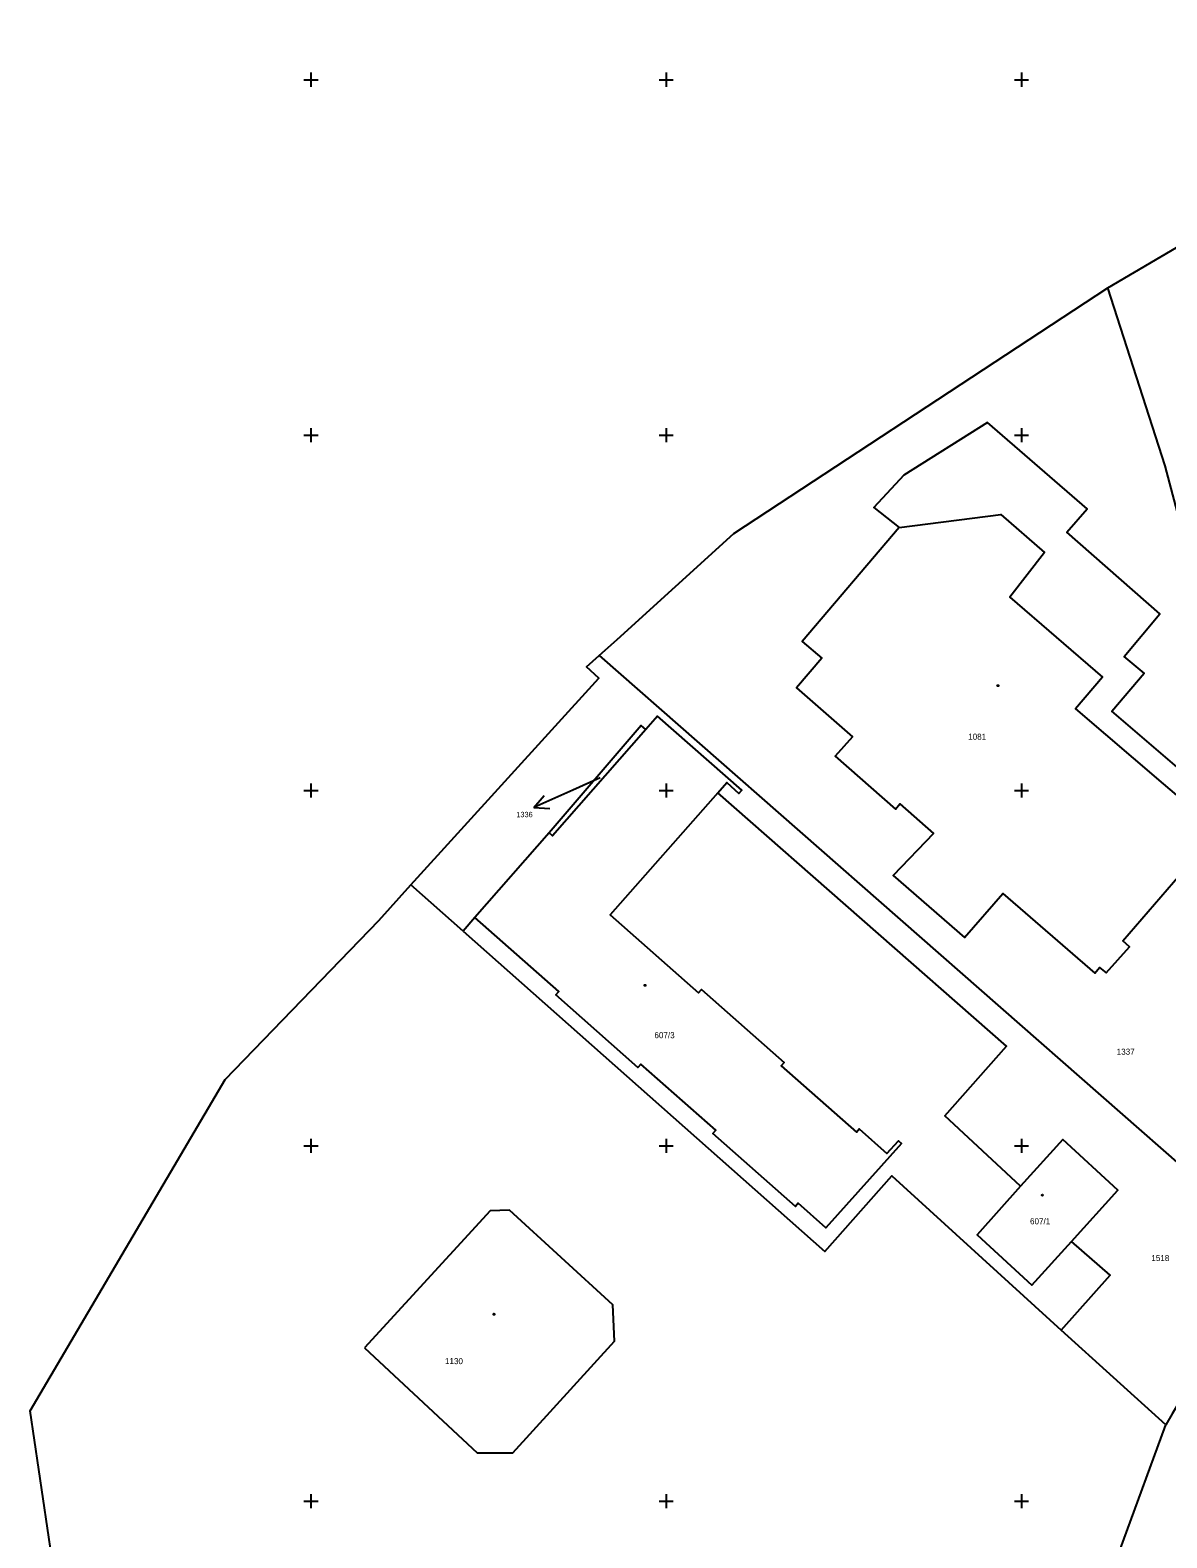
# Model space of a CAD drawing. Extents: x -711234 to -710007, y -1026313 to -1025448.
# Drawn here: x -711044.8 to -710964.8, y -1025852.6 to -1025746.5 of the extents above; entities that cross this region are included whole.
import ezdxf

# ---------------------------------------------------------------- set-up
doc = ezdxf.new("R2010")
doc.units = 0
for name, color, linetype in [('Z_hektometricka_sit', 7, 'Continuous'), ('Z_katastr_cisla_pozemkova', 7, 'Continuous'), ('Z_katastr_cisla_stavebni', 7, 'Continuous'), ('Z_katastr_hranice', 7, 'Continuous'), ('Z_katastr_parcelni_cislo_odkaz', 7, 'Continuous'), ('Z_katastr_vnitrni_kresba', 7, 'Continuous'), ('Z_katastr_znacky_budov', 7, 'Continuous')]:
    doc.layers.add(name, color=color, linetype=linetype)

msp = doc.modelspace()

# ---------------------------------------------------------------- linework, layer by layer
at = {"layer": 'Z_hektometricka_sit'}
for p, q in [((-711025.5, -1025750), (-711024.5, -1025750)), ((-711025, -1025749.5), (-711025, -1025750.5)), ((-711000.5, -1025750), (-710999.5, -1025750)), ((-711000, -1025749.5), (-711000, -1025750.5)), ((-710975.5, -1025750), (-710974.5, -1025750)), ((-710975, -1025749.5), (-710975, -1025750.5)), ((-711025.5, -1025775), (-711024.5, -1025775)), ((-711025, -1025774.5), (-711025, -1025775.5)), ((-711000.5, -1025775), (-710999.5, -1025775)), ((-711000, -1025774.5), (-711000, -1025775.5)), ((-710975.5, -1025775), (-710974.5, -1025775)), ((-710975, -1025774.5), (-710975, -1025775.5)), ((-711025, -1025799.5), (-711025, -1025800.5)), ((-711000, -1025799.5), (-711000, -1025800.5)), ((-710975, -1025799.5), (-710975, -1025800.5)), ((-711025.5, -1025800), (-711024.5, -1025800)), ((-711000.5, -1025800), (-710999.5, -1025800)), ((-710975.5, -1025800), (-710974.5, -1025800)), ((-711025.5, -1025825), (-711024.5, -1025825)), ((-711025, -1025824.5), (-711025, -1025825.5)), ((-711000.5, -1025825), (-710999.5, -1025825)), ((-711000, -1025824.5), (-711000, -1025825.5)), ((-710975.5, -1025825), (-710974.5, -1025825)), ((-710975, -1025824.5), (-710975, -1025825.5)), ((-711025, -1025849.5), (-711025, -1025850.5)), ((-711000, -1025849.5), (-711000, -1025850.5)), ((-710975, -1025849.5), (-710975, -1025850.5)), ((-711025.5, -1025850), (-711024.5, -1025850)), ((-711000.5, -1025850), (-710999.5, -1025850)), ((-710975.5, -1025850), (-710974.5, -1025850))]:
    msp.add_line(p, q, dxfattribs=at)
at = {"layer": 'Z_katastr_hranice'}
for p, q in [((-711004.72, -1025790.51), (-710958.45, -1025831.09)), ((-711008.23, -1025802.99), (-711013.46, -1025808.94)), ((-711014.28, -1025809.91), (-711017.96, -1025806.65)), ((-711013.46, -1025808.94), (-711014.28, -1025809.91)), ((-710964.85, -1025844.62), (-710972.21, -1025837.97))]:
    msp.add_line(p, q, dxfattribs=at)
for points in [[(-710968.93, -1025764.64), (-710955.38, -1025756.68), (-710946.98, -1025752.23), (-710932.82, -1025746.51)], [(-711004.72, -1025790.51), (-711003.46, -1025789.37), (-710995.25, -1025781.93), (-710972.89, -1025767.24), (-710968.93, -1025764.64)], [(-710958.45, -1025831.09), (-710956.97, -1025823.37), (-710960.68, -1025811.62), (-710961.28, -1025808.78), (-710956.91, -1025805.08), (-710961.58, -1025789.66), (-710964.9, -1025777.15), (-710968.93, -1025764.64)], [(-710964.04, -1025798.37), (-710968.65, -1025794.42), (-710966.36, -1025791.75), (-710967.77, -1025790.57), (-710965.26, -1025787.57), (-710971.82, -1025781.82), (-710970.38, -1025780.18), (-710977.39, -1025774.11), (-710983.28, -1025777.81), (-710985.39, -1025780.09), (-710983.6, -1025781.5), (-710990.44, -1025789.51), (-710989.06, -1025790.69), (-710990.83, -1025792.77), (-710986.9, -1025796.22), (-710988.1, -1025797.59), (-710983.87, -1025801.31), (-710983.55, -1025800.95), (-710981.19, -1025803.03), (-710984.03, -1025805.99), (-710979, -1025810.34), (-710976.32, -1025807.24), (-710969.84, -1025812.85), (-710969.5, -1025812.45), (-710969.04, -1025812.84), (-710967.39, -1025811), (-710967.88, -1025810.58), (-710961.19, -1025802.83)], [(-711017.96, -1025806.65), (-711004.74, -1025792.09), (-711005.61, -1025791.31), (-711004.72, -1025790.51)], [(-711001.44, -1025795.71), (-711001.77, -1025795.42), (-711008.23, -1025802.99)], [(-711001.44, -1025795.71), (-711008.01, -1025803.19), (-711008.23, -1025802.99)], [(-710996.37, -1025800.16), (-710995.74, -1025799.44), (-710994.88, -1025800.21), (-710994.68, -1025799.98), (-711000.62, -1025794.77), (-711001.44, -1025795.71)], [(-710996.37, -1025800.16), (-711003.95, -1025808.75), (-710997.72, -1025814.24), (-710997.52, -1025814.01), (-710991.71, -1025819.14), (-710991.91, -1025819.37), (-710986.62, -1025824.03), (-710986.42, -1025823.81), (-710984.47, -1025825.53), (-710983.66, -1025824.64), (-710983.44, -1025824.84), (-710988.77, -1025830.76), (-710990.72, -1025829.04), (-710990.91, -1025829.27), (-710996.72, -1025824.13), (-710996.52, -1025823.91), (-711001.79, -1025819.25), (-711001.99, -1025819.48), (-711007.76, -1025814.37), (-711007.56, -1025814.15), (-711013.46, -1025808.94)], [(-710972.21, -1025837.97), (-710968.75, -1025834.11), (-710971.49, -1025831.73), (-710968.22, -1025828.12), (-710972.1, -1025824.55), (-710975.06, -1025827.85), (-710980.39, -1025822.88), (-710976.06, -1025817.98), (-710996.37, -1025800.16)], [(-710972.26, -1025878.16), (-710977.8, -1025881.46), (-710995.88, -1025889.65), (-710999.94, -1025888.16), (-711024.11, -1025879.36), (-711040.72, -1025866.26), (-711042.93, -1025856.02), (-711044.76, -1025843.64), (-711031.03, -1025820.33), (-711020.22, -1025809.15), (-711017.96, -1025806.65)], [(-711014.28, -1025809.91), (-710988.85, -1025832.44), (-710984.13, -1025827.11), (-710972.21, -1025837.97)], [(-711021.24, -1025839.22), (-711013.3, -1025846.61), (-711010.8, -1025846.59), (-711003.63, -1025838.75), (-711003.75, -1025836.19), (-711011.03, -1025829.52), (-711012.39, -1025829.58), (-711021.24, -1025839.22)], [(-710958.45, -1025831.09), (-710958.6, -1025831.88), (-710958.18, -1025833.56), (-710959.08, -1025835.05), (-710964.39, -1025843.86), (-710964.85, -1025844.62)], [(-710972.26, -1025878.16), (-710970.89, -1025861.14), (-710964.85, -1025844.62)]]:
    msp.add_lwpolyline(points, dxfattribs=at)
at = {"layer": 'Z_katastr_parcelni_cislo_odkaz'}
for p, q in [((-711004.65, -1025799.12), (-711006.57, -1025799.99)), ((-711006.57, -1025799.99), (-711009.31, -1025801.21)), ((-711009.31, -1025801.21), (-711008.6, -1025800.35)), ((-711009.31, -1025801.21), (-711008.19, -1025801.26))]:
    msp.add_line(p, q, dxfattribs=at)
at = {"layer": 'Z_katastr_vnitrni_kresba'}
msp.add_line((-710965.04, -1025799.53), (-710961.96, -1025802.17), dxfattribs=at)
for points in [[(-710983.6, -1025781.5), (-710976.46, -1025780.59), (-710973.39, -1025783.26), (-710975.83, -1025786.39), (-710969.31, -1025792.03), (-710971.21, -1025794.25), (-710965.04, -1025799.53)], [(-710975.06, -1025827.85), (-710978.13, -1025831.27), (-710974.28, -1025834.8), (-710971.49, -1025831.73)]]:
    msp.add_lwpolyline(points, dxfattribs=at)
at = {"layer": 'Z_katastr_znacky_budov'}
for centre in [(-710976.66, -1025792.63), (-711001.49, -1025813.71), (-710973.53, -1025828.47), (-711012.12, -1025836.85)]:
    msp.add_circle(centre, 0.0437, dxfattribs=at)

# ---------------------------------------------------------------- texts
at = {"layer": 'Z_katastr_cisla_pozemkova'}
for s, height, p in [('1336', 0.375, (-711010.55, -1025801.88)), ('1337', 0.425, (-710968.3, -1025818.59)), ('1518', 0.425, (-710965.86, -1025833.11))]:
    msp.add_text(s, height=height, dxfattribs=at).set_placement(p)
at = {"layer": 'Z_katastr_cisla_stavebni'}
for s, p in [('1081', (-710978.75, -1025796.43)), ('607/3', (-711000.83, -1025817.43)), ('607/1', (-710974.4, -1025830.52)), ('1130', (-711015.57, -1025840.36))]:
    msp.add_text(s, height=0.425, dxfattribs=at).set_placement(p)

doc.saveas('drawing.dxf')
